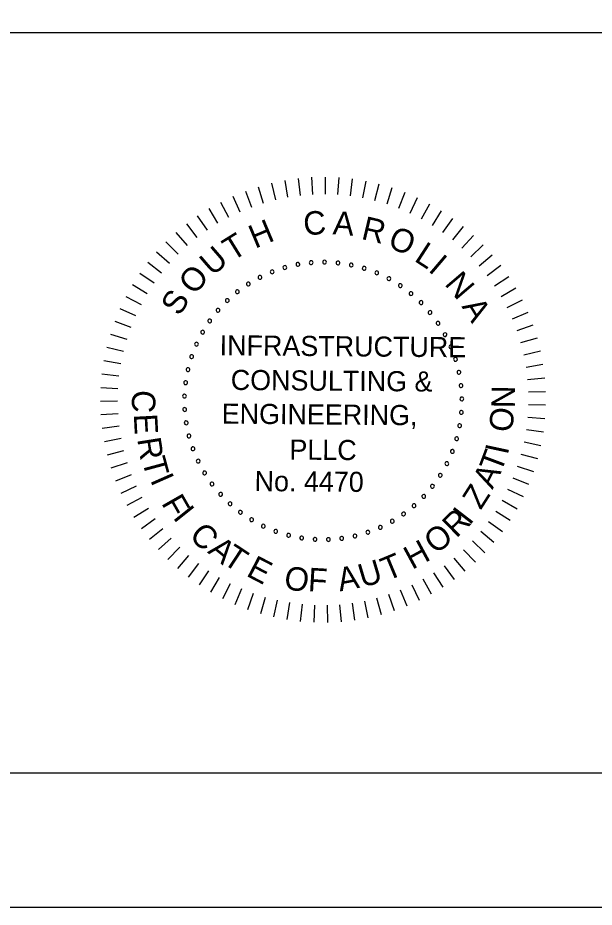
# Model space of a CAD drawing. Extents: x -55.6 to -19.5, y -100.1 to -78.1.
# Drawn here: x -30.386 to -28.243, y -100.121 to -96.816 of the extents above; entities that cross this region are included whole.
import ezdxf

# ---------------------------------------------------------------- set-up
doc = ezdxf.new("R2010")
doc.units = 0
for name, color, linetype in [('BR_BORDER LINES', 7, 'Continuous'), ('BR_TEXT', 7, 'Continuous'), ('Level 31', 7, 'Continuous')]:
    doc.layers.add(name, color=color, linetype=linetype)

msp = doc.modelspace()

# ---------------------------------------------------------------- linework, layer by layer
at = {"layer": 'BR_BORDER LINES'}
for p, q in [((-32.9495, -96.871), (-27.5843, -96.871)), ((-53.7501, -99.6212), (-20.084, -99.6212))]:
    msp.add_line(p, q, dxfattribs=at)
at = {"layer": 'BR_TEXT'}
for p, q in [((-29.4431, -97.4303), (-29.4282, -97.4922)), ((-29.3936, -97.4201), (-29.3826, -97.4828)), ((-29.3437, -97.4129), (-29.3365, -97.4762)), ((-29.2934, -97.4088), (-29.29, -97.4724)), ((-29.2429, -97.4077), (-29.2434, -97.4714)), ((-29.1924, -97.4097), (-29.1969, -97.4733)), ((-29.1422, -97.4148), (-29.1505, -97.478)), ((-29.0924, -97.423), (-29.1045, -97.4855)), ((-29.5396, -97.4597), (-29.5173, -97.5194)), ((-29.4918, -97.4436), (-29.4732, -97.5045)), ((-29.0432, -97.4341), (-29.0591, -97.4958)), ((-28.9947, -97.4483), (-29.0143, -97.5088)), ((-28.9472, -97.4653), (-28.9705, -97.5246)), ((-29.5864, -97.4788), (-29.5605, -97.537)), ((-28.9008, -97.4853), (-28.9277, -97.543)), ((-29.676, -97.5253), (-29.6432, -97.5798)), ((-29.6319, -97.5007), (-29.6025, -97.5571)), ((-28.8557, -97.508), (-28.8861, -97.564)), ((-29.7185, -97.5525), (-29.6824, -97.605)), ((-28.8121, -97.5334), (-28.8458, -97.5875)), ((-28.7701, -97.5615), (-28.8071, -97.6134)), ((-29.7592, -97.5823), (-29.72, -97.6325)), ((-28.73, -97.592), (-28.77, -97.6416)), ((-29.7981, -97.6145), (-29.7559, -97.6622)), ((-28.6917, -97.625), (-28.7347, -97.672)), ((-29.8349, -97.649), (-29.7899, -97.6941)), ((-28.6555, -97.6602), (-28.7013, -97.7045)), ((-29.8696, -97.6857), (-29.8219, -97.728)), ((-29.9019, -97.7245), (-29.8518, -97.7637)), ((-28.6216, -97.6976), (-28.6699, -97.739)), ((-28.59, -97.7369), (-28.6407, -97.7753)), ((-29.9319, -97.7651), (-29.8794, -97.8012)), ((-28.5608, -97.7781), (-28.6138, -97.8134)), ((-29.9593, -97.8075), (-29.9047, -97.8404)), ((-28.5342, -97.821), (-28.5893, -97.853)), ((-29.984, -97.8515), (-29.9276, -97.881)), ((-28.5103, -97.8655), (-28.5672, -97.894)), ((-30.0061, -97.8969), (-29.948, -97.9229)), ((-28.4891, -97.9113), (-28.5477, -97.9363)), ((-30.0253, -97.9436), (-29.9657, -97.966)), ((-28.4708, -97.9584), (-28.5307, -97.9797)), ((-30.0417, -97.9914), (-29.9808, -98.0101)), ((-28.4553, -98.0064), (-28.5165, -98.0241)), ((-30.0551, -98.0401), (-29.9932, -98.055)), ((-28.4428, -98.0553), (-28.505, -98.0693)), ((-30.0655, -98.0895), (-30.0028, -98.1006)), ((-28.4334, -98.1049), (-28.4962, -98.115)), ((-30.0729, -98.1394), (-30.0096, -98.1467)), ((-28.4269, -98.155), (-28.4903, -98.1613)), ((-30.0772, -98.1897), (-30.0136, -98.1931)), ((-28.4236, -98.2054), (-28.4872, -98.2078)), ((-30.0784, -98.2402), (-30.0148, -98.2397)), ((-28.4233, -98.2559), (-28.4869, -98.2544)), ((-30.0766, -98.2906), (-30.0131, -98.2863)), ((-28.4261, -98.3063), (-28.4895, -98.3009)), ((-30.0717, -98.3409), (-30.0086, -98.3327)), ((-28.4319, -98.3564), (-28.4949, -98.3472)), ((-30.0637, -98.3907), (-30.0012, -98.3787)), ((-28.4408, -98.4061), (-28.5031, -98.393)), ((-30.0528, -98.44), (-29.9911, -98.4242)), ((-28.4527, -98.4552), (-28.5141, -98.4383)), ((-30.0388, -98.4885), (-29.9782, -98.469)), ((-28.4676, -98.5034), (-28.5279, -98.4829)), ((-30.0219, -98.5361), (-29.9626, -98.5129)), ((-30.0021, -98.5825), (-29.9444, -98.5558)), ((-28.4854, -98.5506), (-28.5443, -98.5265)), ((-28.5061, -98.5967), (-28.5634, -98.569)), ((-29.9796, -98.6277), (-29.9235, -98.5974)), ((-28.5295, -98.6414), (-28.585, -98.6103)), ((-29.9543, -98.6714), (-29.9002, -98.6378)), ((-28.5556, -98.6847), (-28.6091, -98.6502)), ((-29.9264, -98.7135), (-29.8745, -98.6766)), ((-28.5842, -98.7262), (-28.6356, -98.6885)), ((-29.896, -98.7538), (-29.8464, -98.7138)), ((-29.8632, -98.7922), (-29.8161, -98.7493)), ((-28.6154, -98.7659), (-28.6643, -98.7252)), ((-29.8281, -98.8285), (-29.7838, -98.7828)), ((-28.6489, -98.8037), (-28.6953, -98.76)), ((-29.7909, -98.8625), (-29.7494, -98.8143)), ((-28.6847, -98.8393), (-28.7283, -98.7929)), ((-29.7517, -98.8943), (-29.7132, -98.8436)), ((-28.7624, -98.9037), (-28.8, -98.8523)), ((-28.7226, -98.8727), (-28.7633, -98.8237)), ((-29.7105, -98.9236), (-29.6752, -98.8706)), ((-28.8041, -98.9322), (-28.8385, -98.8787)), ((-29.6677, -98.9504), (-29.6357, -98.8953)), ((-29.6234, -98.9745), (-29.5948, -98.9176)), ((-28.8474, -98.9582), (-28.8785, -98.9026)), ((-29.5776, -98.9958), (-29.5525, -98.9373)), ((-28.9383, -99.0019), (-28.9624, -98.9429)), ((-28.8922, -98.9814), (-28.9198, -98.924)), ((-29.5307, -99.0143), (-29.5092, -98.9544)), ((-29.4826, -99.0299), (-29.4649, -98.9688)), ((-29.4338, -99.0426), (-29.4198, -98.9805)), ((-29.083, -99.0459), (-29.096, -98.9836)), ((-29.0339, -99.0342), (-29.0507, -98.9728)), ((-28.9856, -99.0195), (-29.0061, -98.9592)), ((-29.3842, -99.0523), (-29.374, -98.9894)), ((-29.3342, -99.0589), (-29.3278, -98.9955)), ((-29.2838, -99.0624), (-29.2814, -98.9988)), ((-29.2333, -99.0629), (-29.2348, -98.9993)), ((-29.1829, -99.0603), (-29.1882, -98.9969)), ((-29.1328, -99.0546), (-29.1419, -98.9916))]:
    msp.add_line(p, q, dxfattribs=at)
for centre, start, end in [((-29.3445, -97.7325), 10.6038, 190.6038), ((-29.2951, -97.7258), 5.0653, 185.0653), ((-29.2951, -97.7258), 185.0653, 5.0653), ((-29.2453, -97.7239), 359.5268, 179.5268), ((-29.2453, -97.7239), 179.5268, 359.5268), ((-29.1956, -97.7268), 173.9884, 353.9884), ((-29.1956, -97.7268), 353.9884, 173.9884), ((-29.1463, -97.7345), 348.4499, 168.4499), ((-29.4402, -97.7599), 21.6807, 201.6807), ((-29.4402, -97.7599), 201.6807, 21.6807), ((-29.393, -97.7439), 16.1422, 196.1422), ((-29.393, -97.7439), 196.1422, 16.1422), ((-29.3445, -97.7325), 190.6038, 10.6038), ((-29.1463, -97.7345), 168.4499, 348.4499), ((-29.0981, -97.7469), 162.9114, 342.9114), ((-29.0981, -97.7469), 342.9114, 162.9114), ((-29.0513, -97.7639), 157.373, 337.373), ((-29.0513, -97.7639), 337.373, 157.373), ((-29.4856, -97.7805), 27.2191, 207.2191), ((-29.4856, -97.7805), 207.2191, 27.2191), ((-29.0063, -97.7854), 151.8345, 331.8345), ((-29.0063, -97.7854), 331.8345, 151.8345), ((-29.5694, -97.8342), 38.2961, 218.2961), ((-29.5288, -97.8053), 32.7576, 212.7576), ((-29.5288, -97.8053), 212.7576, 32.7576), ((-28.9636, -97.8111), 146.2961, 326.2961), ((-28.9636, -97.8111), 326.2961, 146.2961), ((-29.607, -97.8668), 43.8345, 223.8345), ((-29.607, -97.8668), 223.8345, 43.8345), ((-29.5694, -97.8342), 218.2961, 38.2961), ((-28.9236, -97.8408), 140.7576, 320.7576), ((-28.9236, -97.8408), 320.7576, 140.7576), ((-28.8866, -97.8742), 135.2191, 315.2191), ((-28.8866, -97.8742), 315.2191, 135.2191), ((-29.6413, -97.903), 49.373, 229.373), ((-29.6413, -97.903), 229.373, 49.373), ((-28.8531, -97.9111), 129.6807, 309.6807), ((-28.8531, -97.9111), 309.6807, 129.6807), ((-29.672, -97.9423), 54.9114, 234.9114), ((-29.672, -97.9423), 234.9114, 54.9114), ((-28.8232, -97.951), 124.1422, 304.1422), ((-28.8232, -97.951), 304.1422, 124.1422), ((-29.6987, -97.9843), 60.4499, 240.4499), ((-29.6987, -97.9843), 240.4499, 60.4499), ((-28.7974, -97.9936), 118.6038, 298.6038), ((-28.7974, -97.9936), 298.6038, 118.6038), ((-29.7213, -98.0288), 65.9884, 245.9884), ((-29.7213, -98.0288), 245.9884, 65.9884), ((-28.7757, -98.0384), 113.0653, 293.0653), ((-28.7757, -98.0384), 293.0653, 113.0653), ((-29.7394, -98.0752), 71.5268, 251.5268), ((-29.7394, -98.0752), 251.5268, 71.5268), ((-28.7585, -98.0852), 107.5268, 287.5268), ((-28.7585, -98.0852), 287.5268, 107.5268), ((-29.753, -98.1231), 77.0653, 257.0653), ((-29.753, -98.1231), 257.0653, 77.0653), ((-28.7459, -98.1334), 101.9884, 281.9884), ((-28.7459, -98.1334), 281.9884, 101.9884), ((-29.7619, -98.1721), 82.6038, 262.6038), ((-29.7619, -98.1721), 262.6038, 82.6038), ((-28.7381, -98.1826), 96.4499, 276.4499), ((-28.7381, -98.1826), 276.4499, 96.4499), ((-29.766, -98.2218), 88.1422, 268.1422), ((-29.766, -98.2218), 268.1422, 88.1422), ((-28.735, -98.2324), 90.9114, 270.9114), ((-28.735, -98.2324), 270.9114, 90.9114), ((-29.7653, -98.2716), 93.6807, 273.6807), ((-29.7653, -98.2716), 273.6807, 93.6807), ((-28.7367, -98.2822), 85.373, 265.373), ((-28.7367, -98.2822), 265.373, 85.373), ((-29.7598, -98.3212), 99.2191, 279.2191), ((-29.7598, -98.3212), 279.2191, 99.2191), ((-28.7432, -98.3316), 79.8345, 259.8345), ((-28.7432, -98.3316), 259.8345, 79.8345), ((-29.7496, -98.3699), 104.7576, 284.7576), ((-29.7496, -98.3699), 284.7576, 104.7576), ((-28.7544, -98.3801), 74.2961, 254.2961), ((-28.7544, -98.3801), 254.2961, 74.2961), ((-29.7346, -98.4175), 110.2961, 290.2961), ((-29.7346, -98.4175), 290.2961, 110.2961), ((-28.7703, -98.4273), 68.7576, 248.7576), ((-28.7703, -98.4273), 248.7576, 68.7576), ((-29.7152, -98.4634), 115.8345, 295.8345), ((-29.7152, -98.4634), 295.8345, 115.8345), ((-28.7907, -98.4728), 63.2191, 243.2191), ((-28.7907, -98.4728), 243.2191, 63.2191), ((-29.6914, -98.5072), 121.373, 301.373), ((-29.6914, -98.5072), 301.373, 121.373), ((-28.8153, -98.5161), 57.6807, 237.6807), ((-28.8153, -98.5161), 237.6807, 57.6807), ((-29.6636, -98.5484), 126.9114, 306.9114), ((-29.6636, -98.5484), 306.9114, 126.9114), ((-28.8441, -98.5568), 52.1422, 232.1422), ((-28.8441, -98.5568), 232.1422, 52.1422), ((-29.6318, -98.5869), 132.4499, 312.4499), ((-29.6318, -98.5869), 312.4499, 132.4499), ((-28.8766, -98.5946), 46.6038, 226.6038), ((-29.5965, -98.622), 137.9884, 317.9884), ((-29.5965, -98.622), 317.9884, 137.9884), ((-28.9126, -98.629), 41.0653, 221.0653), ((-28.8766, -98.5946), 226.6038, 46.6038), ((-29.558, -98.6536), 143.5268, 323.5268), ((-29.558, -98.6536), 323.5268, 143.5268), ((-28.9518, -98.6598), 35.5268, 215.5268), ((-28.9126, -98.629), 221.0653, 41.0653), ((-29.5166, -98.6814), 149.0653, 329.0653), ((-29.5166, -98.6814), 329.0653, 149.0653), ((-28.9937, -98.6867), 29.9884, 209.9884), ((-28.9937, -98.6867), 209.9884, 29.9884), ((-28.9518, -98.6598), 215.5268, 35.5268), ((-29.4727, -98.705), 154.6038, 334.6038), ((-29.4727, -98.705), 334.6038, 154.6038), ((-29.4267, -98.7242), 340.1422, 160.1422), ((-29.0844, -98.7277), 18.9114, 198.9114), ((-29.0381, -98.7094), 24.4499, 204.4499), ((-29.0381, -98.7094), 204.4499, 24.4499), ((-29.4267, -98.7242), 160.1422, 340.1422), ((-29.3791, -98.739), 165.6807, 345.6807), ((-29.3791, -98.739), 345.6807, 165.6807), ((-29.3303, -98.749), 351.2191, 171.2191), ((-29.3303, -98.749), 171.2191, 351.2191), ((-29.2808, -98.7544), 356.7576, 176.7576), ((-29.2808, -98.7544), 176.7576, 356.7576), ((-29.231, -98.7549), 2.2961, 182.2961), ((-29.231, -98.7549), 182.2961, 2.2961), ((-29.1813, -98.7506), 7.8345, 187.8345), ((-29.1813, -98.7506), 187.8345, 7.8345), ((-29.1323, -98.7415), 13.373, 193.373), ((-29.1323, -98.7415), 193.373, 13.373), ((-29.0844, -98.7277), 198.9114, 18.9114)]:
    msp.add_arc(centre, 0.00701, start, end, dxfattribs=at)
at = {"layer": 'Level 31'}
msp.add_lwpolyline([(-55.5834, -100.1211), (-19.5834, -100.1211), (-19.5834, -78.1211), (-55.5834, -78.1211)], close=True, dxfattribs=at)

# ---------------------------------------------------------------- texts
at = {"layer": 'BR_TEXT'}
for s, height, rotation, p in [('C', 0.0872, 4.7281, (-29.3208, -97.6253)), ('A', 0.0872, 355.6981, (-29.2164, -97.6204)), ('R', 0.0872, 346.6681, (-29.1121, -97.6373)), ('H', 0.0872, 22.7882, (-29.5037, -97.6747)), ('O', 0.0872, 337.638, (-29.0143, -97.6672)), ('T', 0.0872, 31.8182, (-29.5885, -97.7224)), ('U', 0.0872, 40.8482, (-29.6618, -97.7785)), ('L', 0.0872, 327.108, (-28.9155, -97.7176)), ('I', 0.0872, 319.578, (-28.8629, -97.7554)), ('O', 0.0872, 49.8782, (-29.7288, -97.8495)), ('N', 0.0872, 310.548, (-28.8021, -97.8062)), ('S', 0.0872, 58.9083, (-29.7842, -97.9277)), ('A', 0.0872, 301.5179, (-28.7371, -97.8886)), ('INFRASTRUCTURE', 0.074771, 359.5268, (-29.6356, -98.0702)), ('CONSULTING &', 0.074771, 359.5268, (-29.5943, -98.1988)), ('N', 0.0872, 89.2085, (-28.5378, -98.2674)), ('C', 0.0872, 267.025, (-29.9592, -98.1976)), ('ENGINEERING,', 0.074771, 359.5268, (-29.6279, -98.3242)), ('O', 0.0872, 83.2085, (-28.5488, -98.3588)), ('E', 0.0872, 273.025, (-29.9548, -98.2892)), ('R', 0.0872, 279.025, (-29.942, -98.3815)), ('PLLC', 0.07477, 359.5268, (-29.3762, -98.4578)), ('T', 0.0872, 69.3954, (-28.5901, -98.5106)), ('I', 0.0872, 77.9093, (-28.5644, -98.4431)), ('T', 0.0872, 285.025, (-29.9246, -98.4602)), ('I', 0.0872, 293.7713, (-29.8949, -98.5333)), ('No. 4470', 0.07477, 359.5268, (-29.5057, -98.5747)), ('A', 0.0872, 63.3954, (-28.6209, -98.5709)), ('Z', 0.0872, 57.3954, (-28.6647, -98.6473)), ('F', 0.0872, 299.7713, (-29.8538, -98.6194)), ('I', 0.0872, 308.5268, (-29.8117, -98.6733)), ('R', 0.0872, 44.5268, (-28.7551, -98.7522)), ('I', 0.0872, 52.3339, (-28.7058, -98.705)), ('C', 0.0872, 314.5268, (-29.7523, -98.7434)), ('O', 0.0872, 38.5268, (-28.8317, -98.8122)), ('A', 0.0872, 320.5268, (-29.6832, -98.802)), ('T', 0.0872, 326.5268, (-29.6287, -98.8404)), ('H', 0.0872, 28.5268, (-28.9198, -98.8682)), ('E', 0.0872, 332.5268, (-29.5401, -98.8882)), ('T', 0.0872, 22.5268, (-29.013, -98.91)), ('U', 0.0872, 16.5268, (-29.1047, -98.9344)), ('O', 0.0872, 350.5268, (-29.4, -98.9371)), ('F', 0.0872, 356.5268, (-29.3085, -98.9462)), ('A', 0.0872, 10.5268, (-29.1887, -98.9479))]:
    msp.add_text(s, height=height, rotation=rotation, dxfattribs=at).set_placement(p)

doc.saveas('drawing.dxf')
